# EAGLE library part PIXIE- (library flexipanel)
PIC microcontroller with 2.4GHz IEEE 802.15.4 transceiver and ZigBee stack Source: www.FlexiPanel.com .. Pixie DS481.pdf
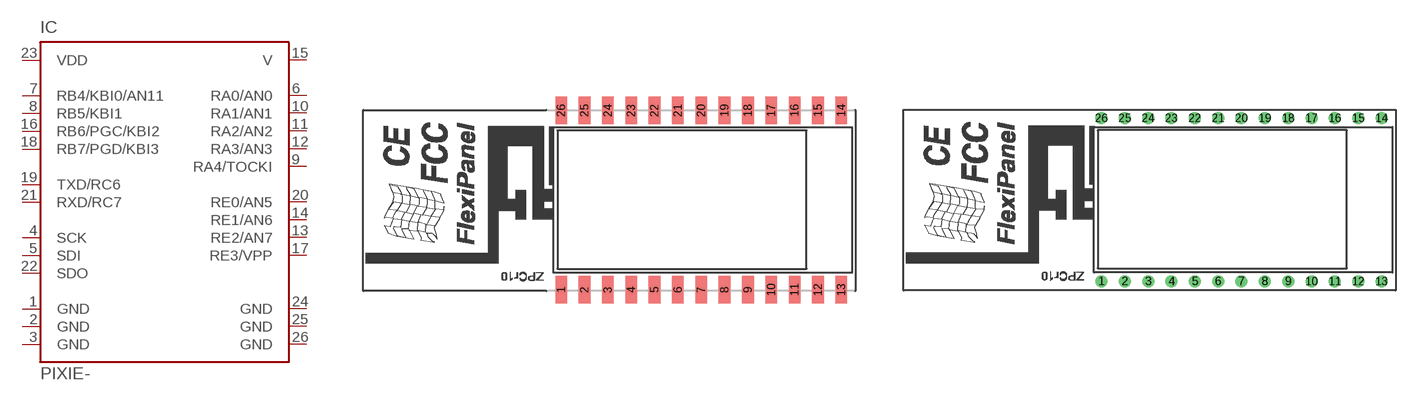
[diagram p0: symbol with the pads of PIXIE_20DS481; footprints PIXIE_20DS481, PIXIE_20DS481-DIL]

Designator prefix IC

## PIXIE-SO (MPN: PIXIE-SO; OC_FARNELL: 1330072; OC_NEWARK: 34M8078)  [PIXIE_20DS481]
1  GND  pwr
2  GND  pwr
3  GND  pwr
4  SCK
5  SDI
6  RA0/AN0
7  RB4/KBI0/AN11
8  RB5/KBI1
9  RA4/TOCKI
10  RA1/AN1
11  RA2/AN2
12  RA3/AN3
13  RE2/AN7
14  RE1/AN6
15  V  in
16  RB6/PGC/KBI2
17  RE3/VPP  in
18  RB7/PGD/KBI3
19  TXD/RC6
20  RE0/AN5
21  RXD/RC7
22  SDO
23  VDD  pwr
24  GND  pwr
25  GND  pwr
26  GND  pwr

## PIXIE-DIL (OC_FARNELL: unknown; OC_NEWARK: unknown)  [PIXIE_20DS481-DIL]
Pads as for PIXIE_20DS481

## Footprint PIXIE_20DS481 (pad centres in mm)
PIC microcontroller with 2.4GHz IEEE 802.15.4 transceiver and ZigBee stack Source: www.FlexiPanel.com .. Pixie DS481.pdf
smd 1.27 x 3: 1 -15.24,-9.761; 2 -12.7,-9.761; 3 -10.16,-9.761; 4 -7.62,-9.761; 5 -5.08,-9.761; 6 -2.54,-9.761; 7 0,-9.761; 8 2.54,-9.761; 9 5.08,-9.761; 10 7.62,-9.761; 11 10.16,-9.761; 12 12.7,-9.761; 13 15.24,-9.761; 14 15.24,9.761; 15 12.7,9.761; 16 10.16,9.761; 17 7.62,9.761; 18 5.08,9.761; 19 2.54,9.761; 20 0,9.761; 21 -2.54,9.761; 22 -5.08,9.761; 23 -7.62,9.761; 24 -10.16,9.761; 25 -12.7,9.761; 26 -15.24,9.761

## Footprint PIXIE_20DS481-DIL (pad centres in mm)
PIC microcontroller with 2.4GHz IEEE 802.15.4 transceiver and ZigBee stack Source: www.FlexiPanel.com .. Pixie DS481.pdf
drill 0.8 pad 1.27 round: 1 -15.24,-8.89; 2 -12.7,-8.89; 3 -10.16,-8.89; 4 -7.62,-8.89; 5 -5.08,-8.89; 6 -2.54,-8.89; 7 0,-8.89; 8 2.54,-8.89; 9 5.08,-8.89; 10 7.62,-8.89; 11 10.16,-8.89; 12 12.7,-8.89; 13 15.24,-8.89; 14 15.24,8.89; 15 12.7,8.89; 16 10.16,8.89; 17 7.62,8.89; 18 5.08,8.89; 19 2.54,8.89; 20 0,8.89; 21 -2.54,8.89; 22 -5.08,8.89; 23 -7.62,8.89; 24 -10.16,8.89; 25 -12.7,8.89; 26 -15.24,8.89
